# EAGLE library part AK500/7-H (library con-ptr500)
CONNECTOR Aug. 2004 / PTR Meßtechnik: Die Bezeichnung der Serie AK505 wurde geändert. Es handelt sich hierbei um AK500 in horizontaler Ausführung.
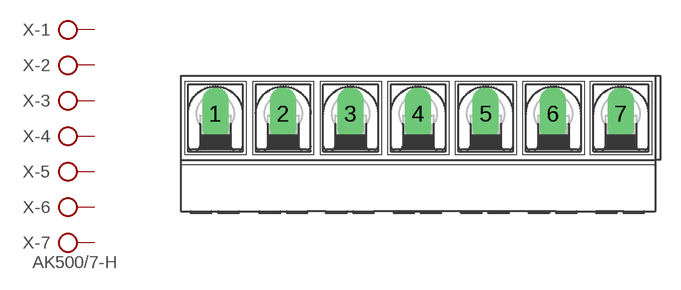
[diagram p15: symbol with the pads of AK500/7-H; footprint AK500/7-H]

Designator prefix X; gates -1=KL -2=KL -3=KL -4=KL -5=KL -6=KL -7=KLV

## AK500/7-H (OC_FARNELL: unknown; OC_NEWARK: unknown)  [AK500/7-H]
1  -1:KL  pas
2  -2:KL  pas
3  -3:KL  pas
4  -4:KL  pas
5  -5:KL  pas
6  -6:KL  pas
7  -7:KL  pas

## Footprint AK500/7-H (pad centres in mm)
CONNECTOR Aug. 2004 / PTR Meßtechnik: Die Bezeichnung der Serie AK505 wurde geändert. Es handelt sich hierbei um AK500 in horizontaler Ausführung.
drill 1.321 long: 1 -15.037,0; 2 -10.008,0; 3 -5.004,0; 4 0,0; 5 5.004,0; 6 10.008,0; 7 15.037,0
